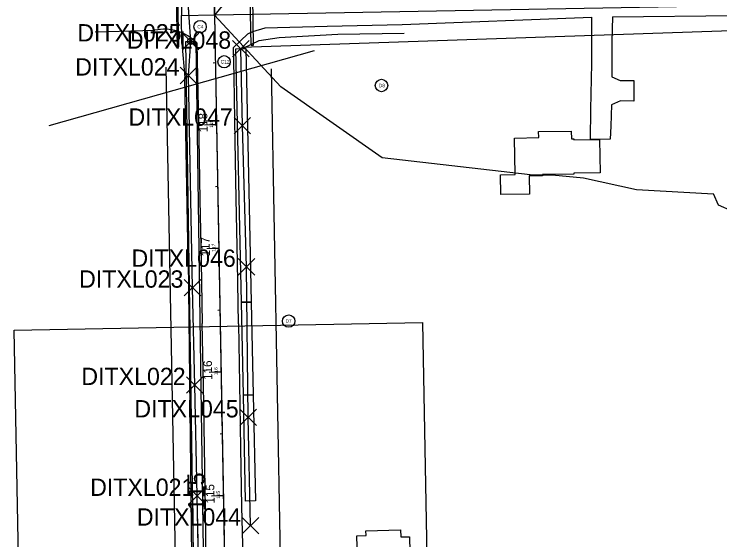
# Model space of a CAD drawing. Extents: x 2287043 to 2296348, y 637947 to 641293.
# Drawn here: x 2287204 to 2287774, y 639437 to 639863 of the extents above; entities that cross this region are included whole.
import ezdxf

# ---------------------------------------------------------------- set-up
doc = ezdxf.new("R2010")
doc.units = 0
for name, color, linetype in [('DR_P_Drainage_Area', 7, 'Continuous'), ('DR_P_Storm_Sewer', 7, 'Continuous'), ('GE_X_CL_100', 7, 'Continuous'), ('GE_X_CL_20', 7, 'Continuous'), ('GE_X_CL_50', 7, 'Continuous'), ('GK_Visualization', 7, 'Continuous'), ('RW_P_Prelim_RW', 7, 'Continuous'), ('SC_Scratch1', 7, 'Continuous'), ('SC_Scratch10', 7, 'Continuous'), ('SC_Scratch11', 7, 'Continuous'), ('SC_Scratch12', 7, 'Continuous'), ('SC_Scratch2', 7, 'Continuous'), ('SC_Scratch4', 7, 'Continuous'), ('SC_Scratch5', 7, 'Continuous'), ('SC_Scratch6', 7, 'Continuous'), ('SC_Scratch7', 7, 'Continuous'), ('SC_Scratch8', 7, 'Continuous')]:
    doc.layers.add(name, color=color, linetype=linetype)

msp = doc.modelspace()

# ---------------------------------------------------------------- linework, layer by layer
at = {"layer": 'DR_P_Drainage_Area'}
for p, q in [((2287365.99, 639861.68), (2287357.3, 640335.57)), ((2287338.73, 639885.77), (2287339.16, 639861.53)), ((2287339.56, 639838.89), (2287339.16, 639861.53)), ((2287339.56, 639838.89), (2287341.88, 639811.24)), ((2287344.62, 639663.86), (2287341.88, 639811.24)), ((2287620.9, 639732.74), (2287501.43, 639746.33)), ((2287344.62, 639663.86), (2287347.81, 639385.32))]:
    msp.add_line(p, q, dxfattribs=at)
for points in [[(2287366.31, 639862.01), (2287948.06, 639872.57), (2287973.81, 639872.7), (2287999.81, 639872.01), (2288025.56, 639870.64), (2288051.56, 639868.51), (2288077.31, 639865.64), (2288102.81, 639862.01), (2288128.31, 639857.64), (2288153.81, 639852.57), (2288179.06, 639846.76), (2288204.06, 639840.2), (2288229.06, 639833.64), (2288254.31, 639827.76), (2288279.81, 639822.7), (2288305.31, 639818.26), (2288331.06, 639814.64), (2288356.81, 639811.7), (2288382.56, 639809.57), (2288408.31, 639808.14), (2288412.26, 639808.03)], [(2287339.16, 639861.53), (2287366.31, 639862.01)], [(2287365.99, 639861.68), (2287378.81, 639153.12), (2287391.95, 638476.45)], [(2287365.99, 639861.68), (2287419.56, 639803.64)], [(2287501.43, 639746.33), (2287419.56, 639803.64)], [(2287620.9, 639732.74), (2287638.64, 639732.74), (2287664.03, 639730.19), (2287706.95, 639720.69), (2287769.27, 639717.31)], [(2287876.22, 639699.81), (2287784.35, 639703.29), (2287773.24, 639708.13), (2287769.27, 639717.31)]]:
    msp.add_lwpolyline(points, dxfattribs=at)
at = {"layer": 'DR_P_Storm_Sewer'}
for p, q in [((2287335.86, 639836.11), (2287334.92, 639886.1)), ((2287337.11, 639836.14), (2287336.17, 639886.13)), ((2287395.47, 639837.54), (2287394.53, 639887.53)), ((2287397.47, 639837.57), (2287396.53, 639887.56)), ((2287335.86, 639836.11), (2287337.11, 639836.14)), ((2287395.47, 639837.54), (2287397.47, 639837.57))]:
    msp.add_line(p, q, dxfattribs=at)
at = {"layer": 'GE_X_CL_100'}
for p, q in [((2287401.6, 637973.38), (2287357.08, 640335.42)), ((2287367.68, 639773.06), (2287357.68, 639772.87)), ((2287369.57, 639673.08), (2287359.57, 639672.89)), ((2287371.45, 639573.1), (2287361.45, 639572.91)), ((2287373.33, 639473.12), (2287363.34, 639472.93))]:
    msp.add_line(p, q, dxfattribs=at)
at = {"layer": 'GE_X_CL_20'}
for p, q in [((2287401.6, 637973.38), (2287357.08, 640335.42)), ((2287366.74, 639823.05), (2287364.74, 639823.02)), ((2287367.68, 639773.06), (2287365.68, 639773.02)), ((2287368.62, 639723.07), (2287366.62, 639723.03)), ((2287369.57, 639673.08), (2287367.57, 639673.04)), ((2287370.51, 639623.09), (2287368.51, 639623.05)), ((2287371.45, 639573.1), (2287369.45, 639573.06)), ((2287372.39, 639523.11), (2287370.39, 639523.07)), ((2287373.33, 639473.12), (2287371.33, 639473.08))]:
    msp.add_line(p, q, dxfattribs=at)
at = {"layer": 'GE_X_CL_50'}
for p, q in [((2287401.6, 637973.38), (2287357.08, 640335.42)), ((2287367.68, 639773.06), (2287362.68, 639772.97)), ((2287367.68, 639773.06), (2287362.68, 639772.97)), ((2287369.57, 639673.08), (2287364.57, 639672.99)), ((2287369.57, 639673.08), (2287364.57, 639672.99)), ((2287371.45, 639573.1), (2287366.45, 639573)), ((2287371.45, 639573.1), (2287366.45, 639573)), ((2287373.33, 639473.12), (2287368.34, 639473.02)), ((2287373.33, 639473.12), (2287368.34, 639473.02))]:
    msp.add_line(p, q, dxfattribs=at)
at = {"layer": 'GK_Visualization'}
for p, q in [((2287346.67, 639840.44), (2287343.84, 639883.89)), ((2287340, 639833.76), (2287353.33, 639847.11)), ((2287340, 639847.11), (2287353.33, 639833.76)), ((2287344.9, 639812.9), (2287346.67, 639840.44)), ((2287380.5, 639827.91), (2287393.84, 639841.26)), ((2287380.5, 639841.26), (2287393.84, 639827.91)), ((2287388.38, 639772.33), (2287387.17, 639834.59)), ((2287338.24, 639806.23), (2287351.57, 639819.58)), ((2287338.24, 639819.58), (2287351.57, 639806.23)), ((2287348.14, 639641.39), (2287344.9, 639812.9)), ((2287381.71, 639765.65), (2287395.05, 639779)), ((2287381.71, 639779), (2287395.05, 639765.65)), ((2287391.67, 639658.26), (2287388.38, 639772.33)), ((2287385, 639651.58), (2287398.34, 639664.93)), ((2287385, 639664.93), (2287398.34, 639651.58)), ((2287393.11, 639536.51), (2287391.67, 639658.26)), ((2287341.48, 639634.71), (2287354.81, 639648.06)), ((2287341.48, 639648.06), (2287354.81, 639634.71)), ((2287349.85, 639562.67), (2287348.14, 639641.39)), ((2287343.18, 639555.99), (2287356.52, 639569.34)), ((2287343.18, 639569.34), (2287356.52, 639555.99)), ((2287351.79, 639473.08), (2287349.85, 639562.67)), ((2287386.45, 639529.84), (2287399.78, 639543.19)), ((2287386.45, 639543.19), (2287399.78, 639529.84)), ((2287394.99, 639449.04), (2287393.11, 639536.51)), ((2287345.13, 639466.41), (2287358.46, 639479.76)), ((2287345.13, 639479.76), (2287358.46, 639466.41)), ((2287352.98, 639418.42), (2287351.79, 639473.08)), ((2287388.33, 639442.36), (2287401.66, 639455.71)), ((2287388.33, 639455.71), (2287401.66, 639442.36))]:
    msp.add_line(p, q, dxfattribs=at)
at = {"layer": 'RW_P_Prelim_RW'}
for p, q in [((2287348.42, 638672.5), (2287326.8, 639819.59)), ((2287433.4, 638674.11), (2287411.84, 639818.25))]:
    msp.add_line(p, q, dxfattribs=at)
at = {"layer": 'SC_Scratch1'}
msp.add_line((2287232.25, 639772.38), (2287446.56, 639833.2), dxfattribs=at)
at = {"layer": 'SC_Scratch10'}
msp.add_lwpolyline([(2287389.19, 639554.57), (2287387.57, 639629.55), (2287395.57, 639629.72), (2287397.18, 639554.74)], close=True, dxfattribs=at)
at = {"layer": 'SC_Scratch11'}
for points in [[(2287349.86, 639354.56), (2287342.67, 639840.38), (2287350.67, 639840.5), (2287357.86, 639354.68)], [(2287387.57, 639629.55), (2287383.17, 639834.5), (2287391.17, 639834.67), (2287395.57, 639629.72)], [(2287391.03, 639468.78), (2287389.19, 639554.57), (2287397.18, 639554.74), (2287399.03, 639468.95)]]:
    msp.add_lwpolyline(points, close=True, dxfattribs=at)
at = {"layer": 'SC_Scratch12'}
msp.add_lwpolyline([(2287512.93, 640010.41), (2287512.93, 639997.11), (2287475.4, 639969.32), (2287423.8, 639927.42), (2287411.29, 639917.27), (2287365.99, 639861.68)], dxfattribs=at)
at = {"layer": 'SC_Scratch2'}
msp.add_lwpolyline([(2287213.53, 639097.15), (2287203.92, 639607.06), (2287533.86, 639613.28), (2287543.47, 639103.37)], close=True, dxfattribs=at)
at = {"layer": 'SC_Scratch4'}
for p, q in [((2287517.44, 639854.21), (2287670.74, 639859.95)), ((2287687.56, 639860.45), (2287794.63, 639861.43)), ((2287269.53, 639848.2), (2287317.69, 639849.58)), ((2287677.01, 639761.24), (2287669.65, 639761.12)), ((2287685.55, 639761.38), (2287677.01, 639761.24))]:
    msp.add_line(p, q, dxfattribs=at)
for points in [[(2287669.65, 639761.12), (2287670.12, 639785.45), (2287670.9, 639822.64), (2287670.91, 639846.74), (2287670.74, 639859.95)], [(2287687.56, 639860.45), (2287686.99, 639840.09), (2287687.03, 639811.84), (2287693.61, 639808.91), (2287704.72, 639808.95), (2287704.73, 639792.12), (2287694.03, 639792.4), (2287686.59, 639789.3), (2287686.08, 639771.95), (2287685.55, 639761.38)], [(2287381.26, 639835.59), (2287392.81, 639846.6), (2287396.72, 639848.61), (2287406.77, 639851.45), (2287456.97, 639852.8), (2287517.44, 639854.21)], [(2287351.59, 639839.25), (2287352.24, 639811.84), (2287353.27, 639762.1), (2287354.12, 639712.32), (2287355.07, 639662.33), (2287355.9, 639612.32)], [(2287385.25, 639612.29), (2287384.37, 639662.14), (2287383.43, 639713.18), (2287383.36, 639713.32), (2287382.49, 639759.97), (2287381.63, 639811.67), (2287381.26, 639835.59)], [(2287362.77, 639262.13), (2287362.38, 639283.92), (2287361.7, 639313.93), (2287360.11, 639371.1), (2287359.2, 639412.59), (2287358.64, 639462.65), (2287357.69, 639512.4), (2287356.88, 639563.05), (2287355.9, 639612.32)], [(2287385.25, 639612.29), (2287386.09, 639563.69), (2287386.86, 639511.87), (2287387.65, 639464.13), (2287388.98, 639413.19), (2287389.34, 639398.71)]]:
    msp.add_lwpolyline(points, dxfattribs=at)
msp.add_arc((2287325.1, 639813.1), 37.22, 44.6175, 101.4782, dxfattribs=at)
at = {"layer": 'SC_Scratch5'}
for points in [[(2287620.11, 639731.7), (2287620.35, 639717.05), (2287597.19, 639716.68), (2287596.94, 639732.72), (2287608.76, 639732.91), (2287608.28, 639762.39), (2287627.91, 639762.71), (2287627.83, 639767.53), (2287654.16, 639767.95), (2287654.26, 639761.71), (2287656.15, 639761.74), (2287656.17, 639760.91), (2287677.01, 639761.24), (2287677.44, 639734.21), (2287656.37, 639733.87), (2287656.38, 639733.16), (2287630.94, 639732.76), (2287630.95, 639731.87)], [(2287536.04, 639395.06), (2287489.75, 639393.99), (2287489.21, 639413.92), (2287481.59, 639413.81), (2287480.77, 639440.81), (2287488.39, 639441), (2287488.11, 639444.94), (2287516.3, 639445.68), (2287516.49, 639439.93), (2287523.45, 639440.09), (2287524.02, 639415.54), (2287516.72, 639415.37), (2287516.77, 639413.38), (2287535.49, 639413.81)]]:
    msp.add_lwpolyline(points, close=True, dxfattribs=at)
at = {"layer": 'SC_Scratch6'}
msp.add_lwpolyline([(2288103.13, 639839.01), (2287989.29, 639855.97), (2287387.83, 639835.49)], dxfattribs=at)
at = {"layer": 'SC_Scratch7'}
for points in [[(2287352.98, 639418.42), (2287351.79, 639473.08), (2287349.85, 639562.67), (2287348.14, 639641.39), (2287344.9, 639812.9), (2287346.67, 639840.44), (2287343.84, 639883.89), (2287341.52, 639973.87), (2287338.09, 640129.44), (2287335.76, 640209.29), (2287332.51, 640226.28)], [(2287389.12, 639835.09), (2287401.86, 639841.32), (2287418.07, 639843.58), (2287465.56, 639846.31), (2287519.05, 639847.08)], [(2287394.99, 639449.04), (2287393.11, 639536.51), (2287391.67, 639658.26), (2287388.38, 639772.33), (2287387.17, 639834.59)]]:
    msp.add_lwpolyline(points, dxfattribs=at)
msp.add_circle((2287346.67, 639840.44), 2.5, dxfattribs=at)
at = {"layer": 'SC_Scratch8'}
for centre in [(2287354.21, 639852.38), (2287373.66, 639824.02), (2287500.84, 639804.83), (2287425.83, 639614.39)]:
    msp.add_circle(centre, 5, dxfattribs=at)

# ---------------------------------------------------------------- texts
at = {"layer": 'GE_X_CL_100'}
msp.add_text('115', height=14, rotation=91.0798, dxfattribs=at).set_placement((2287358.56, 639460.88))
at = {"layer": 'GE_X_CL_20'}
for s, p in [('118', (2287364.73, 639770.67)), ('117', (2287366.61, 639670.57)), ('116', (2287368.5, 639570.64)), ('115', (2287370.38, 639470.67))]:
    msp.add_text(s, height=2.8, rotation=91.0798, dxfattribs=at).set_placement(p)
at = {"layer": 'GE_X_CL_50'}
for s, p in [('118', (2287360.29, 639767.08)), ('118', (2287360.29, 639767.08)), ('117', (2287362.18, 639666.8)), ('117', (2287362.18, 639666.8)), ('116', (2287364.06, 639566.95)), ('116', (2287364.06, 639566.95)), ('115', (2287365.95, 639467)), ('115', (2287365.95, 639467))]:
    msp.add_text(s, height=7, rotation=91.0798, dxfattribs=at).set_placement(p)
at = {"layer": 'GK_Visualization'}
for s, p in [('DITXL025', (2287254.96, 639840.44)), ('DITXL048', (2287295.02, 639834.59)), ('DITXL024', (2287253.3, 639812.9)), ('DITXL047', (2287296.34, 639772.33)), ('DITXL046', (2287298.75, 639658.26)), ('DITXL023', (2287256.43, 639641.39)), ('DITXL022', (2287258.25, 639562.67)), ('DITXL045', (2287301.08, 639536.51)), ('DITXL021', (2287265.35, 639473.08)), ('DITXL044', (2287303.06, 639449.04))]:
    msp.add_text(s, height=14, dxfattribs=at).set_placement(p)
at = {"layer": 'SC_Scratch8'}
for s, p in [('C4', (2287351.98, 639850.98)), ('C12', (2287370.88, 639822.62)), ('D8', (2287498.66, 639803.43)), ('D7', (2287423.24, 639612.99))]:
    msp.add_text(s, height=2.8, dxfattribs=at).set_placement(p)

doc.saveas('drawing.dxf')
